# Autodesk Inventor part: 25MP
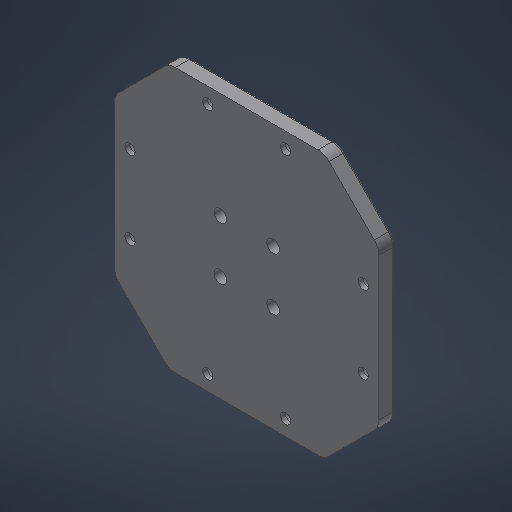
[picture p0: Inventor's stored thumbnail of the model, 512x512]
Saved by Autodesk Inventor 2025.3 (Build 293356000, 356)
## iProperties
Created: 2020-06
Part Number: 25MP
Project: COMMON
Material: Generic
Catalog Web Link: https://www.janelia.org/
Vendor: HHMI: JRC - JET
Document SubType Name: Modeling
Designer: sohna
Density: 1 g/cm^3
Appearance: Default
RuleStatus: InUse
AfterDocSave0: file://Part Number Cleaner
Title: Standard
Author: sohna
Revision Number: 0
LAB/DEPT: COMMON
REQUESTING SCIENTIST: COMMON
DESIGN DEPARTMENT: HHMI: JRC - ID&F
ALTERED ITEM PART NUMBER: N/A
ALTERED ITEM VENDOR: N/A
ALTERED ITEM DESCRIPTION: N/A
Part Number: 7MB28µ×°å
Revision: ÈÎºÎ
Title: 7MB28µ×°å.STEP
Description: STEP AP203
Sending System: SolidWorks 2018
Preprocessor: SwSTEP 2.0
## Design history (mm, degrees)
feature "Ô²½Ç2"
body "Solid1"
